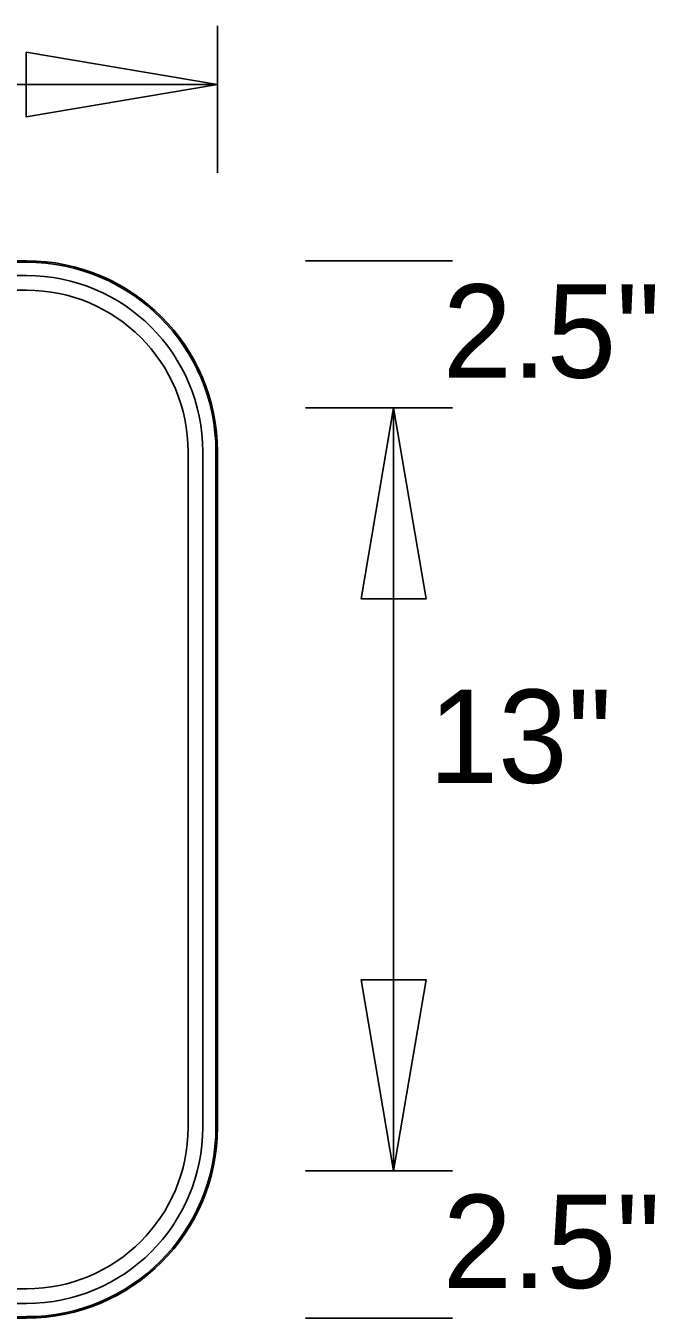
# Model space of a CAD drawing. Extents: x 0 to 770, y 0 to 495.
# Drawn here: x 533.2 to 556.81, y 427.82 to 476.29 of the extents above; entities that cross this region are included whole.
import ezdxf

# ---------------------------------------------------------------- set-up
doc = ezdxf.new("R2010")
doc.units = 0
for name, color, linetype in [('Dimension', 7, 'Continuous'), ('GSBWFill', 7, 'Continuous'), ('GSColorFill', 7, 'Continuous'), ('GSDims', 7, 'Continuous'), ('GSOutline', 7, 'Continuous'), ('TextStructures', 7, 'Continuous')]:
    doc.layers.add(name, color=color, linetype=linetype)

msp = doc.modelspace()

# ---------------------------------------------------------------- linework, layer by layer
at = {"layer": 'Dimension'}
for points in [[(540.391, 474.083), (533.218, 475.298), (533.218, 472.868)], [(547.001, 461.965), (545.786, 454.793), (548.216, 454.793)], [(547.001, 433.336), (548.216, 440.509), (545.786, 440.509)]]:
    msp.add_lwpolyline(points, close=True, dxfattribs=at)
at = {"layer": 'GSBWFill'}
for p, q in [((533.231, 467.473), (507.893, 467.473)), ((533.231, 466.923), (507.893, 466.923)), ((507.893, 466.372), (533.231, 466.372)), ((539.289, 460.313), (539.289, 434.976)), ((539.84, 434.976), (539.84, 460.313)), ((540.391, 434.976), (540.391, 460.313)), ((533.231, 428.917), (507.899, 428.917)), ((507.899, 428.366), (533.231, 428.366)), ((507.893, 427.815), (533.231, 427.815))]:
    msp.add_line(p, q, dxfattribs=at)
for centre, radius, start, end in [((533.231, 460.313), 7.161, 0, 90), ((533.231, 460.313), 6.61, 0, 90), ((533.231, 460.313), 6.059, 0, 90), ((533.231, 434.976), 6.61, 270, 0), ((533.231, 434.976), 6.059, 270, 0), ((533.231, 434.976), 7.161, 270, 0)]:
    msp.add_arc(centre, radius, start, end, dxfattribs=at)
at = {"layer": 'GSColorFill'}
for p, q in [((533.231, 467.473), (507.893, 467.473)), ((533.231, 467.473), (507.893, 467.473)), ((507.893, 467.418), (533.231, 467.418)), ((533.231, 466.923), (507.893, 466.923)), ((507.893, 466.372), (533.231, 466.372)), ((539.289, 460.313), (539.289, 434.976)), ((539.84, 434.976), (539.84, 460.313)), ((540.336, 460.313), (540.336, 434.976)), ((540.391, 434.976), (540.391, 460.313)), ((540.391, 434.976), (540.391, 460.313)), ((533.231, 428.917), (507.899, 428.917)), ((507.899, 428.366), (533.231, 428.366)), ((507.893, 427.815), (533.231, 427.815)), ((533.231, 427.87), (507.894, 427.87)), ((507.894, 427.815), (533.231, 427.815))]:
    msp.add_line(p, q, dxfattribs=at)
for centre, radius, start, end in [((533.231, 460.313), 7.161, 0, 90), ((533.231, 460.313), 7.161, 0, 90), ((533.231, 460.313), 7.105, 0, 90), ((533.231, 460.313), 6.61, 0, 90), ((533.231, 460.313), 6.059, 0, 90), ((533.231, 434.976), 7.161, 270, 0), ((533.231, 434.976), 6.61, 270, 0), ((533.231, 434.976), 6.059, 270, 0), ((533.231, 434.976), 7.161, 270, 0), ((533.231, 434.976), 7.105, 270, 0)]:
    msp.add_arc(centre, radius, start, end, dxfattribs=at)
at = {"layer": 'GSDims'}
for p, q in [((540.391, 470.778), (540.391, 476.286)), ((500.733, 474.083), (540.391, 474.083)), ((543.696, 467.473), (549.204, 467.473)), ((543.696, 461.965), (549.204, 461.965)), ((543.696, 461.965), (549.204, 461.965)), ((547.001, 461.965), (547.001, 433.336)), ((543.696, 433.336), (549.204, 433.336)), ((543.696, 433.336), (549.204, 433.336)), ((543.696, 427.815), (549.204, 427.815))]:
    msp.add_line(p, q, dxfattribs=at)
at = {"layer": 'GSOutline'}
for p, q in [((533.231, 467.473), (507.893, 467.473)), ((533.231, 466.923), (507.893, 466.923)), ((533.231, 466.372), (507.893, 466.372)), ((539.289, 434.976), (539.289, 460.313)), ((539.84, 434.976), (539.84, 460.313)), ((540.391, 434.976), (540.391, 460.313)), ((507.893, 428.917), (533.231, 428.917)), ((507.893, 428.366), (533.231, 428.366)), ((507.893, 427.815), (533.231, 427.815))]:
    msp.add_line(p, q, dxfattribs=at)
for centre, radius, start, end in [((533.231, 460.313), 7.161, 0, 90), ((533.231, 460.313), 6.61, 0, 90), ((533.231, 460.313), 6.059, 0, 90), ((533.231, 434.976), 6.61, 270, 0), ((533.231, 434.976), 6.059, 270, 0), ((533.231, 434.976), 7.161, 270, 0)]:
    msp.add_arc(centre, radius, start, end, dxfattribs=at)

# ---------------------------------------------------------------- texts
at = {"layer": 'TextStructures'}
for s, p in [('2.5"', (548.841, 463.09)), ('13"', (548.318, 447.892)), ('2.5"', (548.841, 428.946))]:
    msp.add_text(s, height=3.5, dxfattribs=at).set_placement(p)

doc.saveas('drawing.dxf')
